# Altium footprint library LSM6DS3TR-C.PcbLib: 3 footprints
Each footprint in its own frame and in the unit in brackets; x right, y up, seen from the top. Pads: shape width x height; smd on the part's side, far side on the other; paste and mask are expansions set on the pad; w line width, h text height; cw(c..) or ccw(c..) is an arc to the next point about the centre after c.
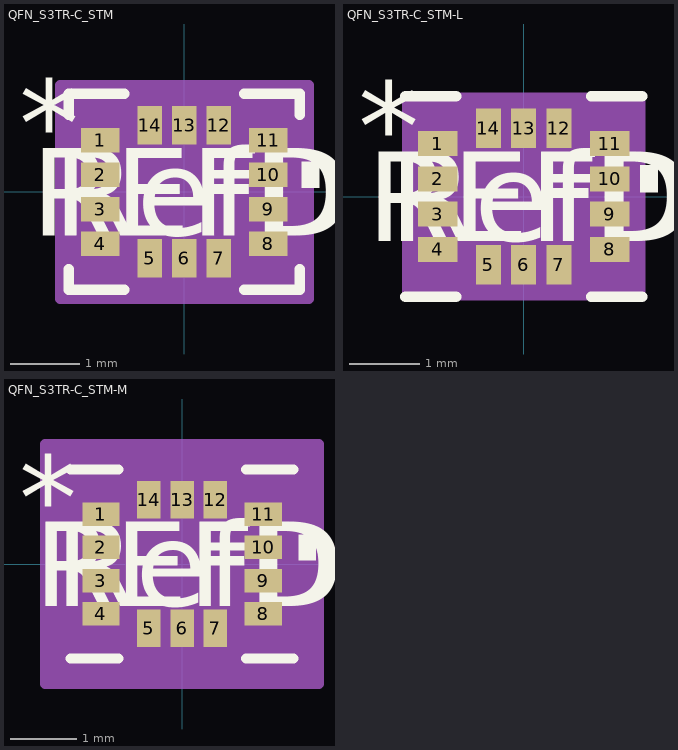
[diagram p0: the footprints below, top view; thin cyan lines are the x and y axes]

## QFN_S3TR-C_STM [mil]
pads (14):
  rect 22x14 smd paste+0 mask+4: 1(-48,29.54) 2(-48,9.85) 3(-48,-9.85) 4(-48,-29.54) 8(48,-29.54) 9(48,-9.85) 10(48,9.85) 11(48,29.54)
  rect 14x22 smd paste+0 mask+4: 5(-19.69,-38) 6(0,-38) 7(19.69,-38) 12(19.69,38) 13(0,38) 14(-19.69,38)
Top Overlay:
  region: 67,17.34 77,17.34 77,2.35 67,2.35
  lines w6: -66,-44.05 -66,-56 -34.21,-56 ; -66,44.05 -66,56 -34.21,56 ; 34.21,-56 66,-56 66,-44.05 ; 34.21,56 66,56 66,44.05
  text "*" at -94.5,14.38 h50
  text "RefDes" at -75,-25 h50
  text "REFDES" at -87.5,-25 h50
Mechanical 13:
  lines w1: -61,1 -11,51 ; -61,-51 61,-51 ; -61,-51 -61,51 ; -61,-51 -61,-51 ; -61,51 61,51 ; -61,51 -61,51 ; 61,-51 61,-51 ; 61,-51 61,51 ; 61,51 61,51 ; -61,-34.53 -61,-24.54 -57,-24.54 -57,-34.53 -61,-34.53 ; -61,-14.85 -61,-4.84 -57,-4.84 -57,-14.85 -61,-14.85 ; -61,4.84 -61,14.85 -57,14.85 -57,4.84 -61,4.84 ; -61,24.54 -61,34.53 -57,34.53 -57,24.54 -61,24.54 ; -24.69,-51 -14.69,-51 -14.69,-47 -24.69,-47 -24.69,-51 ; -24.69,47 -14.69,47 -14.69,51 -24.69,51 -24.69,47 ; -5,-51 5,-51 5,-47 -5,-47 -5,-51 ; -5,47 5,47 5,51 -5,51 -5,47 ; 14.69,-51 24.69,-51 24.69,-47 14.69,-47 14.69,-51 ; 14.69,47 24.69,47 24.69,51 14.69,51 14.69,47 ; 57,-34.53 61,-34.53 61,-24.54 57,-24.54 57,-34.53 ; 57,-14.85 61,-14.85 61,-4.84 57,-4.84 57,-14.85 ; 57,4.84 61,4.84 61,14.85 57,14.85 57,4.84 ; 57,24.54 61,24.54 61,34.53 57,34.53 57,24.54
  text "*" at -51.5,14.38 h50
  text "RefDes2" at -87.5,-25 h50
Mechanical 15:
  region: -34.69,-61 -71,-61 -71,-44.53 -71,44.53 -71,61 -34.69,61 34.69,61 71,61 71,44.53 71,-44.53 71,-61 34.69,-61
  lines w6: -71,-44.53 -71,-61 -34.69,-61 ; -71,-44.53 -71,-44.53 ; -71,-44.53 -71,44.53 ; -71,44.53 -71,44.53 ; -71,44.53 -71,61 -34.69,61 ; -34.69,-61 34.69,-61 ; -34.69,-61 -34.69,-61 ; -34.69,61 -34.69,61 ; -34.69,61 34.69,61 ; 34.69,-61 71,-61 71,-44.53 ; 34.69,-61 34.69,-61 ; 34.69,61 34.69,61 ; 34.69,61 71,61 71,44.53 ; 71,-44.53 71,44.53 ; 71,-44.53 71,-44.53 ; 71,44.53 71,44.53
3D body "QFN_S3TR-C_STM.step": height 34.09, standoff 0, extent -60.98,-50.98 60.98,50.98

## QFN_S3TR-C_STM-L [mil]
pads (14):
  rect 22x14 smd paste+0 mask+4: 1(-48,29.54) 2(-48,9.85) 3(-48,-9.85) 4(-48,-29.54) 8(48,-29.54) 9(48,-9.85) 10(48,9.85) 11(48,29.54)
  rect 14x22 smd paste+0 mask+4: 5(-19.69,-38) 6(0,-38) 7(19.69,-38) 12(19.69,38) 13(0,38) 14(-19.69,38)
Top Overlay:
  region: 65,17.34 75,17.34 75,2.35 65,2.35
  lines w6: -66,-56 -37.76,-56 ; -66,56 -37.76,56 ; 37.76,-56 66,-56 ; 37.76,56 66,56
  text "*" at -92.5,14.38 h50
  text "RefDes" at -75,-25 h50
  text "REFDES" at -87.5,-25 h50
Mechanical 13:
  lines w1: -61,1 -11,51 ; -61,-51 61,-51 ; -61,-51 -61,51 ; -61,-51 -61,-51 ; -61,51 61,51 ; -61,51 -61,51 ; 61,-51 61,-51 ; 61,-51 61,51 ; 61,51 61,51 ; -61,-34.53 -61,-24.54 -57,-24.54 -57,-34.53 -61,-34.53 ; -61,-14.85 -61,-4.84 -57,-4.84 -57,-14.85 -61,-14.85 ; -61,4.84 -61,14.85 -57,14.85 -57,4.84 -61,4.84 ; -61,24.54 -61,34.53 -57,34.53 -57,24.54 -61,24.54 ; -24.69,-51 -14.69,-51 -14.69,-47 -24.69,-47 -24.69,-51 ; -24.69,47 -14.69,47 -14.69,51 -24.69,51 -24.69,47 ; -5,-51 5,-51 5,-47 -5,-47 -5,-51 ; -5,47 5,47 5,51 -5,51 -5,47 ; 14.69,-51 24.69,-51 24.69,-47 14.69,-47 14.69,-51 ; 14.69,47 24.69,47 24.69,51 14.69,51 14.69,47 ; 57,-34.53 61,-34.53 61,-24.54 57,-24.54 57,-34.53 ; 57,-14.85 61,-14.85 61,-4.84 57,-4.84 57,-14.85 ; 57,4.84 61,4.84 61,14.85 57,14.85 57,4.84 ; 57,24.54 61,24.54 61,34.53 57,34.53 57,24.54
  text "*" at -53.5,14.38 h50
  text "RefDes2" at -87.5,-25 h50
Mechanical 15:
  region: -27.69,-55 -65,-55 -65,-37.53 -65,37.53 -65,55 -27.69,55 27.69,55 65,55 65,37.53 65,-37.53 65,-55 27.69,-55
  lines w6: -65,-37.53 -65,-55 -27.69,-55 ; -65,-37.53 -65,-37.53 ; -65,-37.53 -65,37.53 ; -65,37.53 -65,37.53 ; -65,37.53 -65,55 -27.69,55 ; -27.69,-55 27.69,-55 ; -27.69,-55 -27.69,-55 ; -27.69,55 -27.69,55 ; -27.69,55 27.69,55 ; 27.69,-55 65,-55 65,-37.53 ; 27.69,-55 27.69,-55 ; 27.69,55 27.69,55 ; 27.69,55 65,55 65,37.53 ; 65,-37.53 65,37.53 ; 65,-37.53 65,-37.53 ; 65,37.53 65,37.53
3D body "QFN_S3TR-C_STM.step": height 34.09, standoff 0, extent -60.98,-50.98 60.98,50.98

## QFN_S3TR-C_STM-M [mil]
pads (14):
  rect 22x14 smd paste+0 mask+4: 1(-48,29.54) 2(-48,9.85) 3(-48,-9.85) 4(-48,-29.54) 8(48,-29.54) 9(48,-9.85) 10(48,9.85) 11(48,29.54)
  rect 14x22 smd paste+0 mask+4: 5(-19.69,-38) 6(0,-38) 7(19.69,-38) 12(19.69,38) 13(0,38) 14(-19.69,38)
Top Overlay:
  region: 69,17.34 79,17.34 79,2.35 69,2.35
  lines w6: -66,-56 -37.76,-56 ; -66,56 -37.76,56 ; 37.76,-56 66,-56 ; 37.76,56 66,56
  text "*" at -96.5,14.38 h50
  text "RefDes" at -75,-25 h50
  text "REFDES" at -87.5,-25 h50
Mechanical 13:
  lines w1: -61,1 -11,51 ; -61,-51 61,-51 ; -61,-51 -61,51 ; -61,-51 -61,-51 ; -61,51 61,51 ; -61,51 -61,51 ; 61,-51 61,-51 ; 61,-51 61,51 ; 61,51 61,51 ; -61,-34.53 -61,-24.54 -57,-24.54 -57,-34.53 -61,-34.53 ; -61,-14.85 -61,-4.84 -57,-4.84 -57,-14.85 -61,-14.85 ; -61,4.84 -61,14.85 -57,14.85 -57,4.84 -61,4.84 ; -61,24.54 -61,34.53 -57,34.53 -57,24.54 -61,24.54 ; -24.69,-51 -14.69,-51 -14.69,-47 -24.69,-47 -24.69,-51 ; -24.69,47 -14.69,47 -14.69,51 -24.69,51 -24.69,47 ; -5,-51 5,-51 5,-47 -5,-47 -5,-51 ; -5,47 5,47 5,51 -5,51 -5,47 ; 14.69,-51 24.69,-51 24.69,-47 14.69,-47 14.69,-51 ; 14.69,47 24.69,47 24.69,51 14.69,51 14.69,47 ; 57,-34.53 61,-34.53 61,-24.54 57,-24.54 57,-34.53 ; 57,-14.85 61,-14.85 61,-4.84 57,-4.84 57,-14.85 ; 57,4.84 61,4.84 61,14.85 57,14.85 57,4.84 ; 57,24.54 61,24.54 61,34.53 57,34.53 57,24.54
  text "*" at -49.5,14.38 h50
  text "RefDes2" at -87.5,-25 h50
Mechanical 15:
  region: -45.69,-71 -81,-71 -81,-55.53 -81,55.53 -81,71 -45.69,71 45.69,71 81,71 81,55.53 81,-55.53 81,-71 45.69,-71
  lines w6: -81,-55.53 -81,-71 -45.69,-71 ; -81,-55.53 -81,-55.53 ; -81,-55.53 -81,55.53 ; -81,55.53 -81,55.53 ; -81,55.53 -81,71 -45.69,71 ; -45.69,-71 45.69,-71 ; -45.69,-71 -45.69,-71 ; -45.69,71 -45.69,71 ; -45.69,71 45.69,71 ; 45.69,-71 81,-71 81,-55.53 ; 45.69,-71 45.69,-71 ; 45.69,71 45.69,71 ; 45.69,71 81,71 81,55.53 ; 81,-55.53 81,55.53 ; 81,-55.53 81,-55.53 ; 81,55.53 81,55.53
3D body "QFN_S3TR-C_STM.step": height 34.09, standoff 0, extent -60.98,-50.98 60.98,50.98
